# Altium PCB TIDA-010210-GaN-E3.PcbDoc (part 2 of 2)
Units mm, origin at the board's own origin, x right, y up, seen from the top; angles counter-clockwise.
Board outline 75 x 60 mm, 4 copper layers (Top Layer, MidLayer1, MidLayer2, Bottom Layer), stack 1.554 mm thick; 107 components, 49 nets, 409 pads, 513 vias.
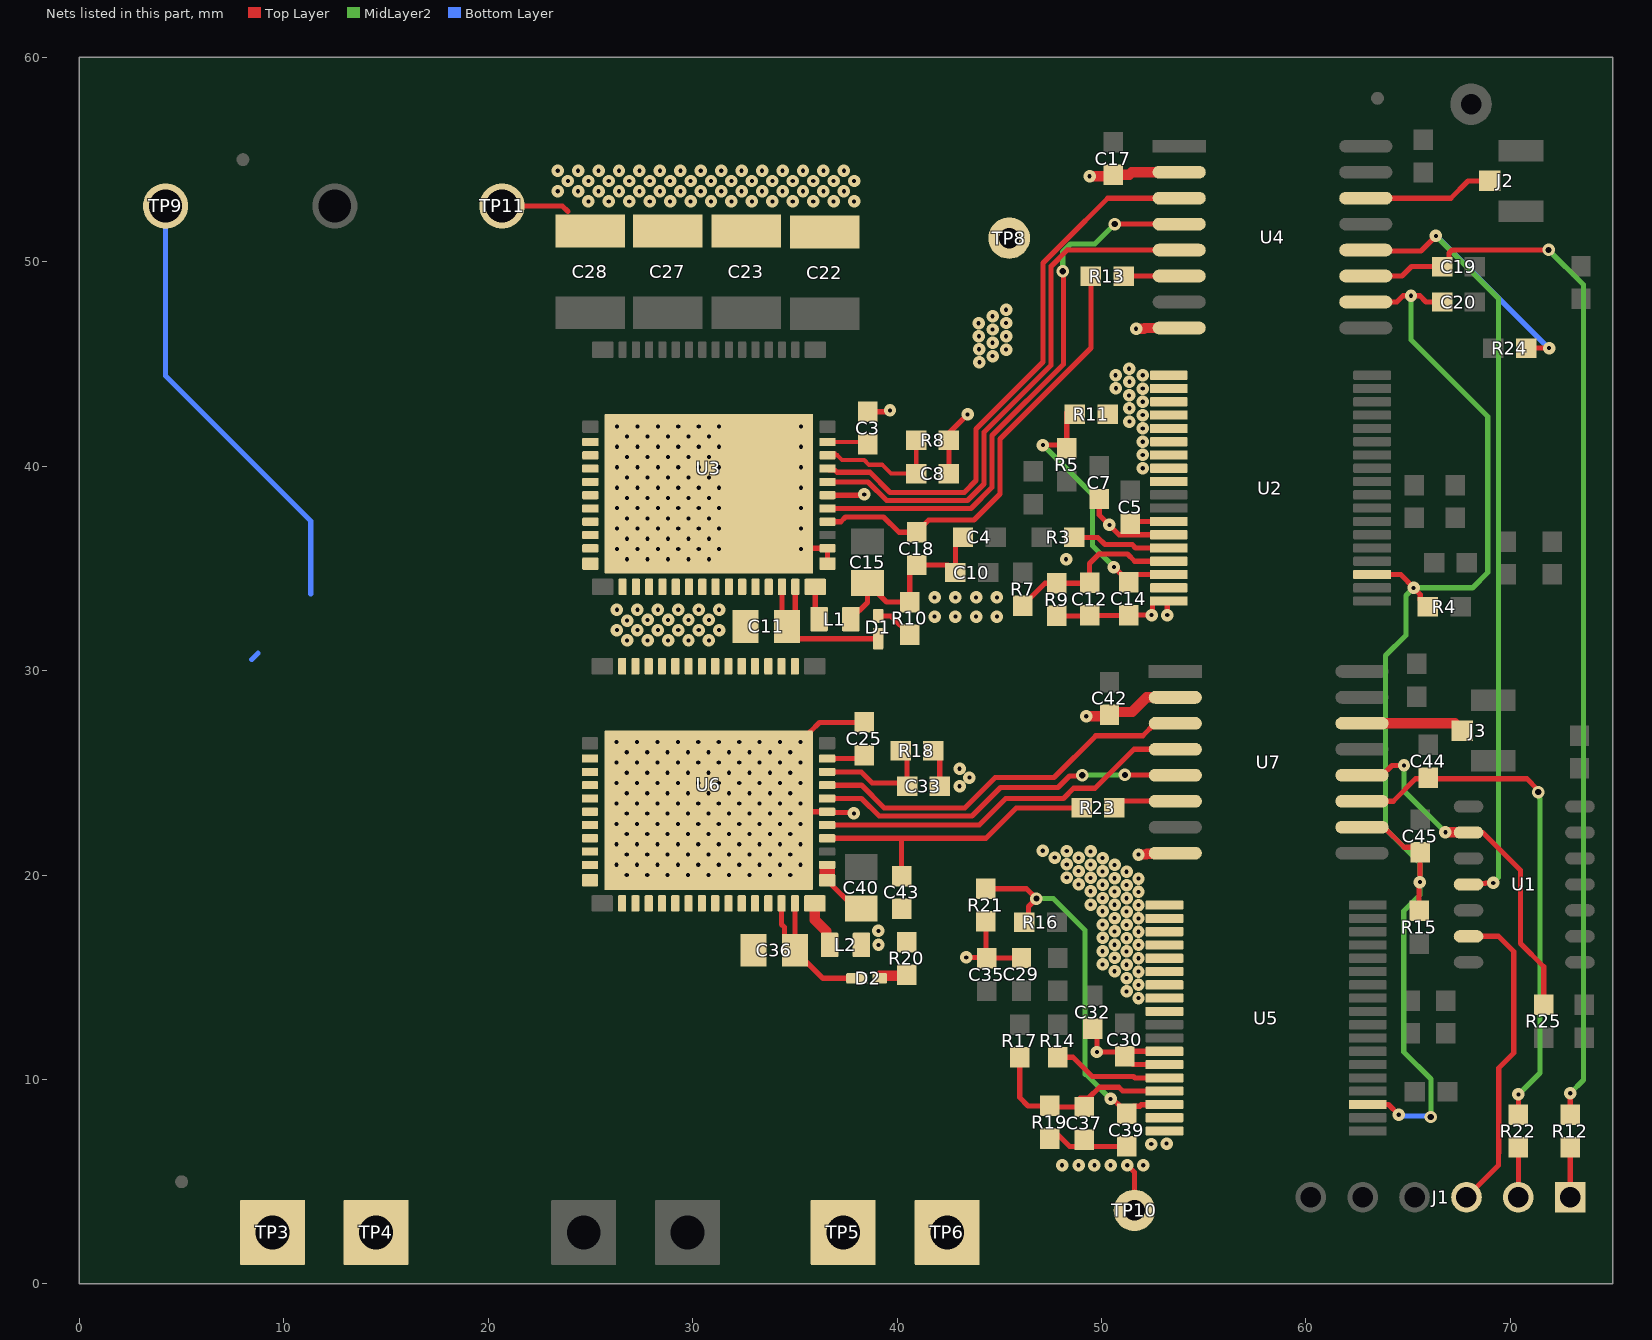
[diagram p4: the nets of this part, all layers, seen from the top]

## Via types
v1: diameter 0.61, hole 0.203, Top Layer to Bottom Layer, tented both sides, 497 vias
v2: diameter 0.61, hole 0.305, Top Layer to Bottom Layer, tented both sides, 16 vias

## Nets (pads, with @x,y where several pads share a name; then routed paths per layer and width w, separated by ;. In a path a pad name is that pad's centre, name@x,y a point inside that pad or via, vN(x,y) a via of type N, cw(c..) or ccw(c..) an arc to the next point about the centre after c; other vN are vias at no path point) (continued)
Low_Rail: C22.2 C23.2 C25.1 C27.2 C28.2 C29.2 C30.2 C32.2 C33.1 C35.2 C36.1 C37.2 C39.2 C40.2 C42.2 C43.2 L2.1 R18.2 R19.1 R20.1 R21.1 TP5.1 TP6.1 TP10.1 TP11.1 U5.19 U5.20 U5.21 U5.22 U5.23 U5.24 U5.25 U5.26 U5.27 U5.30 U5.31 U5.35 U5.36 U6.18 U6.19 U6.20 U6.21 U6.22 U6.23 U6.24 U6.25 U6.26 U6.27 U6.29 U6.30 U6.31 U6.32 U6.33 U6.34 U6.35 U6.36 U6.37 U6.38 U6.39 U6.40 U6.44 U6.45 U6.49 U6.55 U7.2 U7.8 | length 38.3
  Top Layer w0.254: TP11.1@20.676,52.73 23.624,52.73 23.897,52.458 ; v1(35.275,23.507) 35.682,23.1 U6.49@36.575,23.1 36.614,23.061 37.85,23.061 v1(37.89,23.021) ; U6.44@36.575,19.75 37.96,18.365 C40.2@38.251,18.365 ; C25.1@38.401,27.469 36.202,27.469 35.748,27.015 35.748,26.938 U6.55@35.317,26.507 ; C33.1@42.086,24.349 R18.2@42.086,26.074 ; v1(43.382,15.974) 44.312,15.974 C35.2@44.341,15.946 ; R21.1@44.341,17.732 C35.2@44.341,15.946 ; C29.2@45.981,15.946 C35.2@44.341,15.946 ; R19.1@47.681,7.493 48.445,6.729 49.293,6.729 C39.2@51.259,6.729 ; C32.2@49.477,12.578 49.773,12.281 v1(49.773,11.347) 50.926,11.347 C30.2@51.138,11.135 ; v1(51.259,5.809) 51.606,5.463 TP10.1@51.606,3.601 ; U5.31@53.076,10.732 51.541,10.732 51.511,10.762 51.486,10.762 51.138,11.11 C30.2@51.138,11.135 ; U5.30@53.076,11.382 51.385,11.382 C30.2@51.138,11.135 ; U6.55@35.317,26.507 v1(35.275,26.507) U6.55@35.317,26.507
  Top Layer w0.508: v1(49.25,27.768) 50.314,27.768 C42.2@50.39,27.844 50.525,27.979 51.499,27.979 52.213,28.693 U7.2@53.609,28.693 ; v1(51.808,21.007) 52.189,21.007 52.233,21.051 53.587,21.051 U7.8@53.609,21.073
  Top Layer w0.75: U6.44@36.575,19.9 U6.45@36.575,20.3
  other v1: 48.074,5.809 48.875,5.809 49.653,5.809 50.444,5.809 52.038,5.809 52.434,6.843 53.183,6.866 51.808,13.982 51.222,14.314 51.808,14.632 51.222,14.964 50.637,15.296 51.808,15.282 51.222,15.614 50.052,15.628 50.637,15.946 51.808,15.932 50.052,16.278 51.222,16.264 39.09,16.582 51.808,16.582 50.637,16.596 51.222,16.914 50.052,16.928 50.637,17.246 51.808,17.232 39.084,17.27 50.052,17.578 51.222,17.564 51.808,17.882 50.637,17.896 51.222,18.214 50.052,18.228 50.637,18.546 51.808,18.532 49.467,18.561 51.222,18.864 50.052,18.878 51.808,19.182 50.637,19.196 49.467,19.211 50.052,19.528 51.222,19.514 48.881,19.543 51.808,19.832 49.467,19.861 50.637,19.846 48.296,19.875 26.775,20.007 27.775,20.007 28.775,20.007 29.775,20.007 30.775,20.007 31.775,20.007 32.775,20.007 33.775,20.007 34.775,20.007 51.222,20.164 48.881,20.193 50.052,20.178 50.637,20.496 26.275,20.507 27.275,20.507 28.275,20.507 29.275,20.507 30.275,20.507 31.275,20.507 32.275,20.507 33.275,20.507 34.275,20.507 35.275,20.507 48.296,20.525 49.467,20.511 50.052,20.828 47.711,20.857 48.881,20.843 26.775,21.007 27.775,21.007 28.775,21.007 29.775,21.007 30.775,21.007 31.775,21.007 32.775,21.007 33.775,21.007 34.775,21.007 49.467,21.161 47.125,21.189 48.296,21.175 26.275,21.507 27.275,21.507 28.275,21.507 29.275,21.507 30.275,21.507 31.275,21.507 32.275,21.507 33.275,21.507 34.275,21.507 35.275,21.507 26.775,22.007 27.775,22.007 28.775,22.007 29.775,22.007 30.775,22.007 31.775,22.007 32.775,22.007 33.775,22.007 34.775,22.007 26.275,22.507 27.275,22.507 28.275,22.507 29.275,22.507 30.275,22.507 31.275,22.507 32.275,22.507 33.275,22.507 34.275,22.507 35.275,22.507 26.775,23.007 27.775,23.007 28.775,23.007 29.775,23.007 30.775,23.007 31.775,23.007 32.775,23.007 33.775,23.007 34.775,23.007 26.275,23.507 27.275,23.507 28.275,23.507 29.275,23.507 30.275,23.507 31.275,23.507 32.275,23.507 33.275,23.507 34.275,23.507 26.775,24.007 27.775,24.007 28.775,24.007 29.775,24.007 30.775,24.007 31.775,24.007 32.775,24.007 33.775,24.007 34.775,24.007 43.055,24.349 26.275,24.507 27.275,24.507 28.275,24.507 29.275,24.507 30.275,24.507 31.275,24.507 32.275,24.507 33.275,24.507 34.275,24.507 35.275,24.507 43.54,24.768 26.775,25.007 27.775,25.007 28.775,25.007 29.775,25.007 30.775,25.007 31.775,25.007 32.775,25.007 33.775,25.007 34.775,25.007 43.055,25.2 26.275,25.507 27.275,25.507 28.275,25.507 29.275,25.507 30.275,25.507 31.275,25.507 32.275,25.507 33.275,25.507 34.275,25.507 35.275,25.507 26.775,26.007 27.775,26.007 28.775,26.007 29.775,26.007 30.775,26.007 31.775,26.007 32.775,26.007 33.775,26.007 34.775,26.007 26.275,26.507 27.275,26.507 28.275,26.507 29.275,26.507 30.275,26.507 31.275,26.507 32.275,26.507 33.275,26.507 34.275,26.507 24.897,52.953 25.897,52.953 26.897,52.953 27.897,52.953 28.897,52.953 29.897,52.953 30.897,52.953 31.897,52.953 32.897,52.953 33.897,52.953 34.897,52.953 35.897,52.953 36.897,52.953 37.897,52.953 23.397,53.453 24.397,53.453 25.397,53.453 26.397,53.453 27.397,53.453 28.397,53.453 29.397,53.453 30.397,53.453 31.397,53.453 32.397,53.453 33.397,53.453 34.397,53.453 35.397,53.453 36.397,53.453 37.397,53.453 23.897,53.953 24.897,53.953 25.897,53.953 26.897,53.953 27.897,53.953 28.897,53.953 29.897,53.953 30.897,53.953 31.897,53.953 32.897,53.953 33.897,53.953 34.897,53.953 35.897,53.953 36.897,53.953 37.897,53.953 23.397,54.453 24.397,54.453 25.397,54.453 26.397,54.453 27.397,54.453 28.397,54.453 29.397,54.453 30.397,54.453 31.397,54.453 32.397,54.453 33.397,54.453 34.397,54.453 35.397,54.453 36.397,54.453 37.397,54.453
NetC3_2: C3.2 U3.53 | length 2
  Top Layer w0.203: U3.53@36.596,41.185 38.437,41.185 C3.2@38.555,41.067
NetC8_2: C8.2 R8.1 U3.52 | length 6.7
  Top Layer w0.203: U3.52@36.953,40.634 36.694,40.634 U3.52@36.596,40.535 37.076,40.535 37.309,40.303 38.392,40.303 38.625,40.07 39.277,40.07 39.708,39.639 C8.2@40.936,39.639 R8.1@40.936,41.271
NetC11_2: C11.2 D1.1 U3.41 U3.42 | length 9.1
  Top Layer w0.254: U3.41@34.371,34.1 34.371,32.837 C11.2@35.021,32.187 ; C11.2@34.612,32.166 C11.2@35.042,32.166 ; U3.42@35.021,34.1 C11.2@35.021,32.187 ; D1.1@39.075,31.563 35.12,31.563 35.042,31.641 C11.2@35.042,32.166 ; C11.2@35.021,32.187 C11.2@35.042,32.166
NetC12_1: C12.1 R7.1 R9.2 U2.33 | length 8.9
  Top Layer w0.254: R7.1@46.147,33.183 47.242,34.278 R9.2@47.817,34.278 49.389,34.278 C12.1@49.414,34.303 49.414,35.244 49.875,35.705 51.273,35.705 51.627,35.352 U2.33@53.286,35.352
NetC14_1: C14.1 R5.2 R11.2 U2.34 | length 13.6
  Top Layer w0.254: v1(47.135,41.038) 48.131,41.038 R5.2@48.296,40.873 48.296,42.624 R11.2@48.297,42.625 ; v1(50.604,35.068) 51.329,34.343 C14.1@51.329,34.318 51.713,34.702 U2.34@53.286,34.702
  MidLayer2 w0.254: v1(47.135,41.038) 49.563,38.61 49.563,36.109 v1(50.604,35.068)
NetC18_1: C18.1 R13.2 U3.47 | length 22.1
  Top Layer w0.254: U3.47@36.596,37.285 37.243,37.285 37.477,37.519 39.34,37.519 40.09,36.769 C18.1@40.955,36.769 41.551,37.366 43.758,37.366 45.037,38.645 45.037,41.339 49.478,45.78 R13.2@49.478,49.303
NetC19_1: C19.1 R12.2 U4.11 | length 52.9
  Top Layer w0.254: U4.11@62.929,49.303 64.704,49.303 65.164,49.763 C19.1@66.662,49.763 67,50.102 67,50.43 67.149,50.579 v2(71.868,50.579) ; R12.2@72.931,8.282 v1(72.931,9.331)
  MidLayer2 w0.254: v2(71.868,50.579) 73.57,48.877 73.57,9.97 v1(72.931,9.331)
NetC20_1: C20.1 C45.1 R4.2 R15.1 U2.3 U4.10 U5.3 U7.10 | length 64.3
  Top Layer w0.254: U7.10@62.74,22.343 63.824,22.343 64.804,21.364 65.342,21.364 C45.1@65.598,21.109 65.573,21.084 v1(65.573,19.655) 65.534,19.617 R15.1@65.534,18.246 ; U4.10@62.929,48.033 64.442,48.033 64.747,48.338 65.573,48.338 65.878,48.033 C20.1@66.662,48.033 ; U5.3@63.026,8.782 64.037,8.782 v1(64.542,8.278) ; U2.3@63.236,34.702 64.64,34.702 65.29,34.052 v1(65.261,34.052) 65.588,33.725 65.588,33.473 65.965,33.096 R4.2@65.989,33.096
  MidLayer2 w0.254: v1(65.138,48.338) 65.138,46.192 68.896,42.434 68.896,34.805 68.143,34.052 v1(65.261,34.052) 64.886,33.677 64.886,31.736 63.897,30.747 63.897,22.271 65.573,20.595 v1(65.573,19.655) 65.573,19.034 64.783,18.245 64.783,11.347 66.109,10.021 v2(66.109,8.168)
  Bottom Layer w0.254: v1(64.542,8.278) 64.596,8.223 66.054,8.223 v2(66.109,8.168)
NetC25_2: C25.2 U6.53 | length 1.9
  Top Layer w0.254: U6.53@36.575,25.7 38.233,25.7 C25.2@38.401,25.869
NetC33_2: C33.2 R18.1 U6.52 | length 5.9
  Top Layer w0.254: U6.52@36.575,25.05 38.242,25.05 38.785,24.507 40.329,24.507 C33.2@40.486,24.349 R18.1@40.486,26.074
NetC36_2: C36.2 D2.1 U6.41 U6.42 | length 8.1
  Top Layer w0.254: U6.41@34.35,18.615 34.35,17.588 34.493,17.445 34.493,16.995 34.55,16.939 C36.2@35,16.939 ; C36.2@35,16.322 35,16.487 C36.2@35,16.939 ; U6.42@35,18.615 C36.2@35,16.939 ; C36.2@35.001,16.281 C36.2@35.448,15.835 ; C36.2@35.468,15.854 36.372,14.95 D2.1@38.035,14.95
NetC37_1: C37.1 R17.1 R19.2 U5.33 | length 9.8
  Top Layer w0.254: R17.1@45.996,11.091 45.996,9.116 46.4,8.712 R19.2@47.462,8.712 47.518,8.656 C37.1@49.163,8.656 ; C37.1@48.945,9.095 49.366,9.095 49.896,9.625 50.842,9.625 51.035,9.432 U5.33@53.076,9.432
NetC39_1: C39.1 R16.2 R21.2 U5.34 | length 19.1
  Top Layer w0.254: R21.2@44.341,19.332 46.334,19.332 v2(46.812,18.853) 46.429,18.47 46.429,17.899 R16.2@46.222,17.692 ; v1(50.444,9.054) 50.512,8.986 50.623,8.986 50.907,8.702 50.911,8.702 51.259,8.354 C39.1@51.259,8.329 ; C39.1@51.234,8.329 51.234,8.354 51.574,8.694 51.874,8.694 51.947,8.767 53.061,8.767 U5.34@53.076,8.782
  MidLayer2 w0.254: v2(46.812,18.853) 47.636,18.853 49.186,17.304 49.186,10.258 49.239,10.258 v1(50.444,9.054)
NetC43_1: C43.1 R23.2 U6.47 | length 14.9
  Top Layer w0.254: U6.47@36.575,21.8 40.218,21.8 ; C43.1@40.218,19.951 40.218,21.8 ; R23.2@49.026,23.289 45.83,23.289 44.341,21.8 40.218,21.8
NetC44_1: C44.1 R22.2 U7.11 | length 25.7
  Top Layer w0.254: U7.11@62.74,23.613 64.266,23.613 65.371,24.718 65.977,24.718 70.797,24.718 71.36,24.155 v2(71.36,24.059) ; R22.2@70.391,8.282 v1(70.391,9.27)
  MidLayer2 w0.254: v1(70.391,9.27) 71.447,10.326 71.447,23.732 71.428,23.752 71.428,23.991 v2(71.36,24.059)
NetD1_2: D1.2 R10.2 | length 1.9
  Top Layer w0.254: D1.2@39.075,32.678 39.698,32.678 R10.2@40.623,31.753
NetD2_2: D2.2 R20.2 | length 1.3
  Top Layer w0.508: D2.2@39.155,15.084 40.443,15.084 R20.2@40.48,15.121
NetJ1_3: J1.3 U1.6 | length 15.5
  Top Layer w0.254: J1.3@67.851,4.242 69.419,5.809 69.419,6.394 69.429,6.404 69.429,10.561 70.168,11.3 70.168,16.257 69.419,17.006 U1.6@67.952,17.006
NetL1_2: L1.2 U3.43 | length 1.7
  Top Layer w0.254: U3.43@35.996,34.1 35.996,32.712 L1.2@36.186,32.522
NetL2_2: L2.2 U6.43 | length 2.3
  Top Layer w0.508: U6.43@35.975,18.615 35.975,17.807 36.53,17.252 36.53,16.753 L2.2@36.701,16.582
NetR3_1: R3.1 U2.32 | length 4.8
  Top Layer w0.254: R3.1@48.672,36.519 49.815,36.519 50.165,36.17 51.499,36.17 51.667,36.002 U2.32@53.286,36.002
NetR13_1: R13.1 U4.6 | length 2.7
  Top Layer w0.254: R13.1@51.078,49.303 U4.6@53.798,49.303
NetR14_1: R14.1 U5.32 | length 5.6
  Top Layer w0.254: R14.1@47.853,11.091 48.611,11.091 49.547,10.154 51.562,10.154 51.634,10.082 U5.32@53.076,10.082
NetR23_1: R23.1 U7.6 | length 2.8
  Top Layer w0.254: R23.1@50.842,23.629 53.593,23.629 U7.6@53.609,23.613
NetU3_48: U3.48 U4.4 | length 27.7
  Top Layer w0.254: U3.48@36.596,37.935 43.609,37.935 44.643,38.97 44.643,41.502 48.133,44.992 48.133,49.507 v2(48.098,49.542) ; v2(50.643,51.843) U4.4@53.798,51.843
  MidLayer2 w0.254: v2(48.098,49.542) 48.098,50.487 48.477,50.865 49.665,50.865 v2(50.643,51.843)
NetU3_50: U3.50 U4.5 | length 27
  Top Layer w0.254: U3.50@36.596,39.235 38.583,39.235 39.489,38.329 43.446,38.329 44.25,39.133 44.25,41.665 47.527,44.942 47.527,49.778 48.322,50.573 U4.5@53.798,50.573
NetU3_51: U3.51 U4.3 | length 28
  Top Layer w0.254: U3.51@36.596,39.885 36.669,39.812 36.945,39.812 37.055,39.702 38.673,39.702 39.652,38.723 43.283,38.723 43.856,39.296 43.856,41.828 47.133,45.105 47.133,49.941 48.159,50.967 50.305,53.113 U4.3@53.798,53.113
NetU6_48: U6.48 U7.4 | length 18.6
  Top Layer w0.254: U6.48@36.575,22.45 44.017,22.45 45.317,23.75 48.134,23.75 48.634,24.25 49.683,24.25 51.586,26.153 U7.4@53.609,26.153
NetU6_50: U6.50 U7.5 | length 18.2
  Top Layer w0.254: U6.50@36.575,23.75 38.265,23.75 39.124,22.891 43.66,22.891 45.051,24.283 47.866,24.283 48.432,24.848 49.022,24.848 v2(49.057,24.883) ; v2(51.141,24.9) 53.592,24.9 U7.5@53.609,24.883
  MidLayer2 w0.254: v2(49.057,24.883) 49.065,24.892 51.133,24.892 v2(51.141,24.9)
NetU6_51: U6.51 U7.3 | length 19.2
  Top Layer w0.254: U6.51@36.575,24.4 38.252,24.4 39.367,23.285 43.313,23.285 44.804,24.776 47.679,24.776 49.721,26.818 52.014,26.818 52.619,27.423 U7.3@53.609,27.423
O\C\_\H\S\_\I\S\O\: R24.2 U1.4 U4.12 | length 46.9
  Top Layer w0.254: U4.12@62.929,50.573 62.972,50.53 65.622,50.53 v1(66.355,51.264) ; U1.4@67.952,19.546 67.996,19.589 68.753,19.589 68.781,19.617 v1(69.162,19.617) ; R24.2@70.769,45.78 v1(71.889,45.78)
  MidLayer2 w0.254: v1(66.355,51.264) 69.419,48.2 69.419,19.898 69.162,19.641 v1(69.162,19.617)
  Bottom Layer w0.254: v1(66.355,51.264) 66.38,51.264 71.864,45.78 v1(71.889,45.78)
O\C\_\L\S\_\I\S\O\: R25.2 U1.2 U7.12 | length 17.9
  Top Layer w0.254: U7.12@62.74,24.883 63.73,24.883 64.215,25.368 v1(64.796,25.368) ; U1.2@67.952,22.086 68.644,22.086 70.49,20.24 70.49,16.657 71.63,15.518 R25.2@71.63,13.653
  Top Layer w0.508: v1(66.821,22.093) 67.945,22.093 U1.2@67.952,22.086
  MidLayer2 w0.254: v1(64.796,25.368) 64.796,24.118 v1(66.821,22.093)
PWM_HS_ISO: J1.1 R12.1 | length 2.4
  Top Layer w0.254: J1.1@72.931,4.242 R12.1@72.931,6.682
PWM_LS_ISO: J1.2 R22.1 | length 2.4
  Top Layer w0.254: J1.2@70.391,4.242 R22.1@70.391,6.682
SW_Rail: C3.1 C4.2 C5.2 C7.2 C8.1 C10.2 C11.1 C12.2 C14.2 C15.2 C17.2 C18.2 L1.1 R8.2 R9.1 R10.1 R11.1 TP3.1 TP4.1 TP8.1 TP9.1 U2.19 U2.20 U2.21 U2.22 U2.23 U2.24 U2.25 U2.26 U2.27 U2.30 U2.31 U2.35 U2.36 U3.18 U3.19 U3.20 U3.21 U3.22 U3.23 U3.24 U3.25 U3.26 U3.27 U3.29 U3.30 U3.31 U3.32 U3.33 U3.34 U3.35 U3.36 U3.37 U3.38 U3.39 U3.40 U3.44 U3.45 U3.49 U3.55 U4.2 U4.8 U6.2 U6.3 U6.4 U6.5 U6.6 U6.7 U6.8 U6.9 U6.10 U6.11 U6.12 U6.13 U6.14 U6.15 | length 60.9
  Top Layer w0.254: v1(35.296,35.952) 35.329,35.985 U3.45@36.596,35.985 U3.44@36.596,35.235 ; U3.49@36.596,38.585 38.357,38.585 v1(38.391,38.619) ; L1.1@37.736,32.522 38.555,33.342 C15.2@38.555,34.285 39.487,33.353 R10.1@40.623,33.353 40.623,34.838 C18.2@40.955,35.169 42.481,35.169 42.831,34.82 C10.2@42.849,34.802 42.85,34.803 42.85,36.17 43.199,36.519 C4.2@43.224,36.519 ; C3.1@38.555,42.667 39.589,42.667 v1(39.652,42.73) ; C8.1@42.536,39.639 R8.2@42.536,41.271 42.536,41.624 v1(43.446,42.534) ; R9.1@47.817,32.678 49.389,32.678 C12.2@49.414,32.703 51.315,32.703 C14.2@51.329,32.718 v1(52.447,32.718) 52.492,32.763 52.492,33.304 52.59,33.402 U2.36@53.286,33.402 53.217,33.333 v1(53.217,32.719) ; C7.2@49.889,38.398 49.889,37.623 50.86,36.652 U2.31@53.286,36.652 ; C5.2@51.462,37.194 51.569,37.302 U2.30@53.286,37.302
  Top Layer w0.508: v1(49.414,54.186) 50.501,54.186 C17.2@50.564,54.25 51.353,54.25 51.487,54.383 U4.2@53.798,54.383 ; v1(51.689,46.725) 52.07,46.725 52.108,46.763 U4.8@53.798,46.763
  Bottom Layer w0.254: TP9.1@4.216,52.73 4.216,44.427 11.317,37.327 11.317,33.75 ; 8.432,30.546 8.735,30.849
  other v1: 26.796,31.482 27.796,31.482 28.796,31.482 29.796,31.482 30.796,31.482 26.296,31.982 27.296,31.982 28.296,31.982 29.296,31.982 30.296,31.982 31.296,31.982 26.796,32.452 27.796,32.482 28.796,32.482 29.796,32.482 30.796,32.482 41.836,32.643 42.851,32.643 43.866,32.643 44.881,32.643 26.296,32.982 27.296,32.982 28.296,32.982 29.296,32.982 30.296,32.982 31.296,32.982 41.836,33.583 42.851,33.583 43.866,33.583 44.881,33.583 26.796,35.452 27.796,35.452 28.796,35.452 29.796,35.452 30.796,35.452 48.268,35.452 26.296,35.952 27.296,35.952 28.296,35.952 29.296,35.952 30.296,35.952 31.296,35.952 26.796,36.452 27.796,36.452 28.796,36.452 29.796,36.452 30.796,36.452 26.296,36.952 27.296,36.952 28.296,36.952 29.296,36.952 30.296,36.952 31.296,36.952 35.296,36.952 50.381,37.131 26.796,37.452 27.796,37.452 28.796,37.452 29.796,37.452 30.796,37.452 26.296,37.952 27.296,37.952 28.296,37.952 29.296,37.952 30.296,37.952 31.296,37.952 35.296,37.952 26.796,38.452 27.796,38.452 28.796,38.452 29.796,38.452 30.796,38.452 26.296,38.952 27.296,38.952 28.296,38.952 29.296,38.952 30.296,38.952 31.296,38.952 35.296,38.952 26.796,39.452 27.796,39.452 28.796,39.452 29.796,39.452 30.796,39.452 52.018,39.902 26.296,39.952 27.296,39.952 28.296,39.952 29.296,39.952 30.296,39.952 31.296,39.952 35.296,39.952 26.796,40.452 27.796,40.452 28.796,40.452 29.796,40.452 30.796,40.452 52.018,40.552 26.296,40.952 27.296,40.952 28.296,40.952 29.296,40.952 30.296,40.952 31.296,40.952 35.296,40.952 52.018,41.202 26.796,41.452 27.796,41.452 28.796,41.452 29.796,41.452 30.796,41.452 52.018,41.852 26.296,41.952 27.296,41.952 28.296,41.952 29.296,41.952 30.296,41.952 31.296,41.952 35.296,41.952 51.36,42.184 52.018,42.502 51.36,42.834 52.018,43.152 51.347,43.469 50.702,43.816 52.018,43.802 51.36,44.134 50.689,44.451 52.018,44.452 51.347,44.769 44.026,45.087 44.671,45.39 44.013,45.722 45.329,45.707 44.671,46.04 44,46.357 45.329,46.357 44.671,46.69 43.987,46.992 45.329,47.007 44.671,47.34 45.329,47.657
TEMP_HS_ISO: J2.1 U4.14 | length 6.4
  Top Layer w0.254: U4.14@62.929,53.113 67.079,53.113 67.921,53.956 J2.1@68.985,53.956
TEMP_LS_ISO: J3.1 U7.14 | length 5
  Top Layer w0.508: U7.14@62.74,27.423 67.282,27.423 J3.1@67.637,27.068
pads on no net: FID1.1 FID2.1 FID3.1 J2.2@70.51,55.456 J2.3@70.51,52.456 J3.2@69.162,28.568 J3.3@69.162,25.568 U1.3 U1.8 U1.11 U3.1 U3.16 U3.17 U3.28 U3.54 U6.1 U6.16 U6.17 U6.28 U6.54

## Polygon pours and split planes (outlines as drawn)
Low_Rail on MidLayer1 "MidLayer1-Low_Rail" (solid, remove dead copper, pour order 140): 12.294,39.167 18.247,45.12 18.318,51.626 23.092,56.4 36.134,56.4 38.036,54.497 38.036,30.825 43.493,25.368 46.351,25.368 48.781,27.798 48.781,29.881 49.546,30.646 51.63,30.646 53.275,30.646 54.162,29.76 54.162,7.419 52.204,5.461 46.601,5.461 44.977,7.085 44.977,9.499 36.269,18.208 35.89,17.829 44.429,9.089 44.341,1 37.646,1 32.104,6.542 25.429,6.542 12.294,19.678 12.294,27.613
SW_Rail on MidLayer1 "SW_RAIL_L02_P133" (solid, remove dead copper, pour order 133): 35.021,33.182 35.108,33.182 37.122,31.168 37.173,31.22 42.596,31.22 43.488,32.111 53.106,32.111 54.613,33.618 54.613,56.126 54.441,56.126 53.643,56.924 50.008,56.924 48.902,55.818 43.54,50.455 43.54,43.812 43.045,43.317 37.904,43.317 35.876,43.317 35.876,43.245 35,42.368 35.021,42.348
GND_ISO on MidLayer1 "GND_ISO_L02_P096" (solid, remove dead copper, pour order 96): 58.842,4.236 60.691,6.085 61.395,6.085 62.113,6.804 62.113,56.924 63.686,58.496 72.72,58.496 74.581,56.635 74.581,3.165 72.501,1.085 58.842,1.085
Low_Rail on Top Layer "LOW_RAIL_L01_P104" (solid, remove dead copper, pour order 104): 35.773,1 35.773,6.202 23.388,18.587 23.388,27.122 24.465,28.195 34.594,28.195 36.121,26.669 36.121,17.374 44.485,9.01 44.485,1.144 44.341,1
SW_Rail on Top Layer "SW_RAIL_L01_P151" (solid, pour order 151): 52.375,34.239 52.375,32.512 54.204,32.512 54.204,34.239
SW_Rail on Top Layer "SW_RAIL_L01_P148" (solid, remove dead copper, pour order 148): 40.227,33.182 43.177,33.182 43.177,35.258 42.733,35.702 39.734,35.702 37.535,33.503 37.535,32.097 38.143,32.097 38.144,32.618 38.708,33.182
SW_Rail on Top Layer "SW_RAIL_L01_P147" (solid, remove dead copper, pour order 147): 45.19,32.083 45.198,33.773 44.988,33.983 41.552,33.983 41.316,33.747 41.316,31.66 41.756,31.22 42.596,31.22 43.488,32.111 43.516,32.083
Low_Rail on Top Layer "Top Layer-Low_Rail" (solid, remove dead copper, pour order 144): 50.229,21.65 52.06,19.82 54.207,19.82 54.207,18.846 54.207,13.388 53.952,13.133 52.088,13.133 51.43,13.792 48.752,16.47 48.752,18.772 46.309,21.215 46.309,21.513 46.446,21.65 49.187,21.65
Low_Rail on Top Layer "LOW_RAIL_L01_P146" (solid, remove dead copper, pour order 146): 38.051,16.117 38.051,17.41 37.888,17.573 37.235,17.573 36.979,17.829 36.979,18.599 37.302,18.922 40.336,18.922 40.623,18.635 40.623,16.592 40.148,16.117
Low_Rail on Top Layer "LOW_RAIL_L01_P145" (solid, remove dead copper, pour order 145): 43.287,23.658 43.905,24.276 43.905,24.704 42.241,26.368 41.963,26.368 41.963,23.969 42.273,23.658
Low_Rail on Top Layer "LOW_RAIL_L01_P139" (solid, remove dead copper, pour order 139): 46.358,7.315 46.569,7.529 48.735,7.529 49.057,7.206 51.662,7.206 51.984,7.529 51.984,8.393 52.093,8.502 54.141,8.502 54.251,8.392 54.162,8.303 54.162,7.419 52.204,5.461 46.591,5.461 46.323,5.729
SW_Rail on Top Layer "SW_RAIL_L01_P134" (solid, remove dead copper, pour order 134): 54.162,39.053 52.298,39.053 51.64,39.712 51.64,41.397 50.047,42.989 50.047,45.222 54.173,45.222 54.417,44.978 54.417,39.308
GND_ISO on Top Layer "GND_ISO_L01_P130" (solid, remove dead copper, pour order 130): 64.963,28.269 70.168,28.269 70.168,29.972 69.81,30.329 67.093,30.329 65.978,29.214 62.759,29.214 62.421,28.876 62.421,28.391 62.553,28.264
GND_ISO on Top Layer "GND_ISO_L01_P129" (solid, remove dead copper, pour order 129): 62.771,10.258 67.511,10.258 67.837,10.584 67.837,13.629 67.887,13.629 68.471,14.214 69.033,14.214 69.245,14.002 69.217,13.974 69.217,12.306 68.952,12.042 68.952,7.213 68.371,6.632 67.012,6.632 66.513,7.132 66.513,7.795 66.795,8.078 66.795,9.508 66.458,9.845 62.771,9.845
12V_ISO on Top Layer "12V_ISO_L01_P128" (solid, remove dead copper, pour order 128): 62.335,11.403 62.335,10.732 67.244,10.732 67.319,10.807 67.319,11.786 66.841,12.264 65.133,12.258 64.278,11.403
no net on Top Layer "NONET_L01_P127" (solid, remove dead copper, pour order 127): 62.335,11.514 62.335,10.574 62.321,10.561
GND_ISO on Top Layer "GND_ISO_L01_P126" (solid, remove dead copper, pour order 126): 66.794,13.127 69.03,13.127 69.245,13.342 69.245,14.002 68.934,14.312 66.786,14.312 65.361,15.737 64.449,15.737 64.449,18.887 64.244,19.093 64.225,19.074 62.077,19.074 62.077,13.629 62.335,13.371 66.55,13.371
SW_Rail on Top Layer "SW_RAIL_L01_P120" (solid, remove dead copper, pour order 120): 35.276,29.666 35.276,30.498 34.842,30.932 34.785,30.875 33.87,30.875 33.476,31.27 33.476,34.279 34.086,34.89 35.786,34.89 35.786,42.588 35.113,43.261 25.249,43.261 24.315,42.326 24.315,30.714 25.362,29.666
High_Rail on Top Layer "HIGH_RAIL_L01_P117" (solid, remove dead copper, pour order 117): 31.341,1 31.391,1.049 31.391,5.078 21.699,14.77 19.962,16.507 19.962,42.356 23.161,45.555 37.451,45.555 38.401,46.506 38.401,48.148 38.154,48.395 21.561,48.395 12.497,39.331 12.497,19.435 22.905,9.026 22.905,1
Low_Rail on Top Layer "LOW_RAIL_L01_P111" (solid, remove dead copper, pour order 111): 23.282,51.41 22.941,51.751 22.941,55.016 23.324,55.399 37.667,55.399 38.53,54.536 38.53,51.67 38.273,51.414
GND_ISO on Top Layer "GND_ISO_L01_P100" (solid, remove dead copper, pour order 100): 63.951,6.085 64.661,6.796 64.661,7.541 64.346,7.856 63.993,7.856 63.993,8.005 63.653,8.346 63.585,8.278 62.113,8.278 62.113,6.394 62.421,6.085
GND_ISO on Top Layer "GND_ISO_L01_P099" (solid, remove dead copper, pour order 99): 61.717,21.109 61.742,21.084 63.993,21.084 63.993,21.061 64.542,20.512 64.542,19.391 63.946,18.795 63.946,12.248 63.569,11.871 62.274,11.871 62.077,12.068 62.077,19.545 61.717,19.905
GND_ISO on Top Layer "GND_ISO_L01_P098" (solid, remove dead copper, pour order 98): 62.771,31.993 63.07,31.694 63.405,31.688 63.631,31.914 64.136,32.418 64.136,34.142 62.335,34.142 62.335,32.4
GND_ISO on Top Layer "GND_ISO_L01_P097" (solid, remove dead copper, pour order 97): 68.079,38.602 68.531,39.053 68.531,44.979 68.118,45.392 62.802,45.392 62.462,45.052 62.462,38.189 62.929,37.723 63.814,37.723 64.693,38.602
SW_Rail on Bottom Layer "Bottom Layer-SW_Rail" (solid, remove dead copper, pour order 152): 49.836,35.275 50.733,34.378 51.127,34.378 51.36,34.611 51.36,34.93 50.008,36.282 50.008,38.604 47.893,40.719 47.893,40.977 47.418,41.452 46.812,41.452 46.658,41.297 46.658,40.982 49.281,38.359 49.283,36.251 48.077,36.251 47.817,35.99 47.817,35.442 48.231,35.028 49.589,35.028
SW_Rail on Bottom Layer "SW_RAIL_L04_P118" (solid, remove dead copper, pour order 118): 7.226,1 7.226,30.992 10.245,34.01 38.91,34.01 38.91,30.636 38.226,29.951 11.78,29.951 10.414,28.585 10.414,9.437 16.101,3.75 16.101,1
Low_Rail on Bottom Layer "LOW_RAIL_L04_P131" (solid, remove dead copper, pour order 131): 48.077,19.133 48.417,19.472 50.284,19.472 50.466,19.289 50.466,18.554 49.563,17.651 49.563,8.932 50.926,7.569 50.926,6.37 50.459,5.903 47.462,5.903 47.233,6.132 47.233,6.819 48.752,8.337 48.752,17.37 48.062,18.059 48.062,19.118
GND_ISO on Bottom Layer "GND_ISO_L04_P125" (solid, remove dead copper, pour order 125): 58.842,4.236 60.691,6.085 61.395,6.085 62.113,6.804 62.113,56.924 63.686,58.496 72.72,58.496 74.581,56.635 74.581,3.165 72.501,1.085 58.842,1.085
SW_Rail on Bottom Layer "SW_RAIL_L04_P107" (solid, remove dead copper, pour order 107): 22.352,44.384 24.425,46.456 36.449,46.456 38.89,44.015 38.89,31.389 38.169,30.668 22.941,30.668 22.316,31.293 22.352,31.329
Low_Rail on Bottom Layer "LOW_RAIL_L04_P110" (solid, remove dead copper, pour order 110): 22.247,27.016 23.495,28.264 37.361,28.264 38.785,26.84 38.785,17.894 35.814,14.922 25.016,14.923 22.247,17.692
SW_Rail on MidLayer2 "SW_RAIL_L03_P132" (solid, remove dead copper, pour order 132): 23.594,29.793 37.712,29.793 39.138,31.22 42.596,31.22 43.459,32.083 53.078,32.083 54.523,33.528 54.523,56.216 54.351,56.216 53.643,56.924 49.281,56.924 43.54,51.182 43.54,43.812 42.988,43.261 37.961,43.261 23.563,43.261 22.403,42.1 22.403,30.985
Low_Rail on MidLayer2 "LOW_RAIL_L03_P141" (solid, remove dead copper, pour order 141): 48.779,27.734 48.779,29.879 49.546,30.646 51.692,30.646 53.275,30.646 54.162,29.76 54.162,7.419 52.204,5.461 46.601,5.461 44.977,7.085 44.977,9.499 37.477,16.999 23.092,16.999 23.06,16.967 22.454,17.573 22.352,17.573 22.352,27.145 23.402,28.195 40.666,28.195 43.493,25.368 46.413,25.368

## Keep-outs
Keep-Out Layer:
  text ".Layer_Name" at 11.481,-35.478 h1.52

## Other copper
Top Layer:
  text ".Layer_Name" at 11.557,-35.63 h1.52
MidLayer1:
  pour cut-out: 25.241,42.869 25.841,43.469 31.872,43.469 32.335,43.006 32.335,31.034 31.104,29.804 26.487,29.804 25.26,31.031
  text ".Layer_Name" at 11.532,-35.58 h1.52
MidLayer2:
  text ".Layer_Name" at 11.43,-35.529 h1.52
Bottom Layer:
  text ".Layer_Name" at 11.532,-35.58 h1.52

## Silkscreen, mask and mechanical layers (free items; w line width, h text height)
Top Overlay:
  circle w0.254: c14.828,11.3 r2.25
  circle w0.254: c14.8,46.36 r2.25
  circle w0.254: c45.072,28.8 r2.25
  lines w0.254: 41.103,28.683 41.596,28.19 ; 41.242,44.459 41.735,43.966 ; 41.597,28.18 41.597,30.174 ; 41.607,28.18 42.1,28.674 ; 41.736,44.013 41.736,43.956 ; 41.736,45.95 41.736,43.956 ; 42.239,44.45 41.746,43.957 41.746,43.956 41.736,43.956
  text ".PRJ_Number" at 1.517,57.15 h3.05
  text "VER: .PCB_Rev" at 25.841,57.15 h3.05
  text "V+" at 11.325,49.175 h2.54
  text "SW" at 2.075,48.775 h2.54
  text "V-" at 20.111,48.663 h2.54
  text "12V" at 68.175,39.066 h0.64
  text "12V" at 37.395,37.438 h0.64
  text "12V" at 38.922,21.665 h0.64 r90
  text "5V" at 64.719,5.359 h1.27
  text "AGND" at 58.039,5.258 h1.27
  text "12V" at 61.824,5.232 h1.27
  text "PWM1A" at 74.625,5.182 h1.27 r90
  text "FAULT" at 68.986,5.156 h1.27 r90
  text "PWM1B" at 72.085,5.156 h1.27 r90
  text "V+" at 26.34,4.877 h1.52
  text "V-" at 39.268,4.862 h1.52
  text "VSW" at 10.414,4.801 h1.52
  text ".Layer_Name" at 11.659,-35.681 h1.52
Bottom Overlay:
  lines w0.152: 11.074,44.907 11.709,44.247 ; 11.709,44.247 11.684,44.272 11.43,44.272 11.709,44.552 11.709,44.247
  lines w0.381: 52.294,8.89 12.294,8.89 12.294,48.89 52.294,48.89
  text "HeatSink" at 9.931,44.221 h0.64 r270
  text "PWM1B" at 70.027,5.524 h1.27 r270
  text "12V" at 62.452,5.512 h1.27 r270
  text "5V" at 64.922,5.486 h1.27 r270
  text "PWM1A" at 72.695,5.486 h1.27 r270
  text "FAULT" at 67.437,5.461 h1.27 r270
  text "AGND" at 59.868,5.385 h1.27 r270
  text "V+" at 28.118,4.902 h1.52
  text "V-" at 40.97,4.862 h1.52
  text "VSW" at 13.614,4.821 h1.52
  text ".Layer_Name" at 11.582,-35.402 h1.52
Top Paste:
  text ".Layer_Name" at 11.481,-35.478 h1.52
Bottom Paste:
  text ".Layer_Name" at 11.481,-35.478 h1.52
Top Solder:
  text ".Layer_Name" at 11.481,-35.478 h1.52
Bottom Solder:
  rectangle: 12.497,9.093 52.095,48.692
  text ".Layer_Name" at 11.481,-35.478 h1.52
Drill Guide:
  text ".Layer_Name" at 11.481,-35.58 h1.52
M1 Board Outline:
  lines w0.127: 13.3,11.3 cw(c14.8,11.3) 14.8,12.8 cw(c14.8,11.3) 16.3,11.3 cw(c14.8,11.3) 14.8,9.8 cw(c14.8,11.3) 13.3,11.3 ; 13.3,46.3 cw(c14.8,46.3) 14.8,47.8 cw(c14.8,46.3) 16.3,46.3 cw(c14.8,46.3) 14.8,44.8 cw(c14.8,46.3) 13.3,46.3 ; 43.6,28.8 cw(c45.1,28.8) 45.1,30.3 cw(c45.1,28.8) 46.6,28.8 cw(c45.1,28.8) 45.1,27.3 cw(c45.1,28.8) 43.6,28.8
  lines w0.15: 0,0 75,0 75,60 0,60 0,0
M2 Board Dimensions:
  rectangle: -3.048,-20.911 0.127,-17.736
  rectangle: 0,-24.099 9.525,-20.924
  lines w0.178: -3.175,-17.749 -3.175,-24.099 22.225,-24.099 22.225,-17.749 ; -3.048,-20.911 22.352,-20.911 ; -3.048,-17.736 22.352,-17.736 ; 0,-24.099 0,-17.749 ; 3.175,-24.099 3.175,-17.749 ; 9.525,-24.099 9.525,-17.749 ; 15.875,-24.099 15.875,-17.749
M3 3D STEP Top:
  text ".Layer_Name" at 11.481,-35.478 h1.52
M5 Assembly Top:
  circle w0.254: c50.084,27.875 r0.193
  lines w0.254: -10.592,-37.298 157.048,-37.298 ; -10.592,-32.134 157.099,-32.134 ; -10.592,-26.969 -10.592,-42.463 91.135,-42.463 157.099,-42.463 157.099,-26.969 -10.579,-26.969 -10.579,-42.463 29.439,-42.463 ; 52.019,-42.463 52.019,-26.969 ; 84.201,-32.134 84.201,-26.969 ; 105.537,-32.134 105.537,-26.969 ; 121.336,-42.628 121.336,-37.476
  text "COMPONENTS MARKED 'DNP' SHOULD NOT BE POPULATED." at 26.124,-21.762 h0.46
  text "ASSEMBLY VARIANT:" at 26.111,-24.696 h0.46
  text ".VariantName" at 52.426,-24.696 h0.46
  text "PCB VIEWED FROM TOP SIDE" at -8.979,-30.326 h0.46
  text "BOARD #:" at 53.924,-30.326 h0.46
  text ".PRJ_Number" at 67.78,-30.326 h0.46
  text "REV:" at 89.23,-30.326 h0.46
  text ".PCB_Rev" at 96.634,-30.326 h0.46
  text "SVN REV:" at 110.515,-30.326 h0.46
  text ".VersionControl_RevNumber" at 123.368,-30.326 h0.46
  text ".Layer_Name" at 11.285,-35.463 h0.46
  text "TID #:" at 53.924,-35.491 h0.46
  text ".TID" at 67.78,-35.491 h0.46
  text "LAYER NAME =" at -8.979,-35.529 h0.46
  text "PLOT NAME =" at -8.979,-40.706 h0.46
  text ".plot_File_Name" at 11.481,-40.706 h0.46
  text "GENERATED    :" at 53.975,-40.706 h0.46
  text ".Print_Date" at 76.06,-40.706 h0.46
  text ".Print_Time" at 94.577,-40.706 h0.46
  text "TEXAS INSTRUMENTS" at 126.695,-40.706 h0.46
M6 Assembly Bottom:
  circle w0.254: c72.923,5.029 r0.234
  lines w0.254: -10.604,-32.146 157.086,-32.146 ; -10.554,-37.311 157.086,-37.311 ; 25.159,-42.641 25.159,-37.489 ; 40.957,-32.146 40.957,-26.982 ; 62.293,-32.146 62.293,-26.982 ; 94.475,-42.476 94.475,-26.982 ; 117.056,-42.476 157.074,-42.476 157.074,-26.982 -10.604,-26.982 -10.604,-42.476 55.359,-42.476 157.086,-42.476 157.086,-26.982
  text "COMPONENTS MARKED 'DNP' SHOULD NOT BE POPULATED." at 156.769,-21.851 h0.46
  text ".VariantName" at 130.251,-24.797 h0.46
  text "ASSEMBLY VARIANT:" at 156.642,-24.797 h0.46
  text ".VersionControl_RevNumber" at 23.127,-30.339 h0.46
  text "SVN REV:" at 35.979,-30.339 h0.46
  text ".PCB_Rev" at 49.86,-30.339 h0.46
  text "REV:" at 57.264,-30.339 h0.46
  text ".PRJ_Number" at 78.715,-30.339 h0.46
  text "BOARD #:" at 92.57,-30.339 h0.46
  text "PCB VIEWED FROM BOTTOM SIDE" at 155.473,-30.339 h0.46
  text ".Layer_Name" at 146.667,-34.879 h0.46
  text "LAYER NAME =" at 155.207,-35.148 h0.46
  text ".TID" at 78.715,-35.503 h0.46
  text "TID #:" at 92.57,-35.503 h0.46
  text "TEXAS INSTRUMENTS" at 19.799,-40.719 h0.46
  text ".Print_Time" at 51.918,-40.719 h0.46
  text ".Print_Date" at 70.434,-40.719 h0.46
  text "GENERATED    :" at 92.519,-40.719 h0.46
  text ".plot_File_Name" at 135.014,-40.719 h0.46
  text "PLOT NAME =" at 155.473,-40.719 h0.46
M9 Title Sheet:
  drawing of 57 lines, arcs and shapes, not listed
  text "1" at 15.617,190.455 h1.78
  text "2" at 79.007,190.455 h1.78
  text "3" at 142.236,190.455 h1.78
  text "4" at 205.905,190.455 h1.78
  text "5" at 269.38,190.455 h1.78
  text "6" at 333.007,190.455 h1.78
  text "A" at -13.754,161.423 h1.78
  text "A" at 362.166,161.423 h1.78
  text "B" at -13.754,100.971 h1.78
  text "B" at 362.166,100.971 h1.78
  text "C" at 362.166,40.646 h1.78
  text "PROJECT TITLE:" at 284.95,-6.624 h1.14
  text ".PRJ_Title" at 286.22,-10.01 h1.78
  text "DESIGNED FOR:" at 284.95,-14.269 h1.14
  text ".PRJ_Customer" at 286.22,-17.825 h1.78
  text "D" at -13.754,-19.552 h1.78
  text "D" at 362.166,-19.552 h1.78
  text "FILE NAME:" at 284.95,-21.889 h1.14
  text ".PCB_File_Name_No_Path" at 286.22,-24.937 h1.78
  text "Texas Instruments (TI) and/or its licensors do not warrant the accuracy or completeness of this specification" at 158.725,-29.048 h1.14
  text "ENGINEER:" at 284.95,-29.255 h1.14
  text "LAYOUT BY:" at 323.177,-29.255 h1.14
  text "or any information contained therein. TI and/or its licensors do not warrant that this design will meet" at 157.582,-31.909 h1.14
  text ".PRJ_Engineer" at 286.22,-33.192 h1.78
  text ".PCB_Layout" at 324.46,-33.192 h1.78
  text "the specifications, will be suitable for your application or fit for any particular purpose, or will operate in" at 157.582,-34.771 h1.14
  text "ALTIUM DESIGNER VERSION:" at 323.177,-37.129 h1.14
  text "an implementation. TI and/or its licensors do not warrant that the design is production worthy. You should" at 157.582,-37.633 h1.14
  text "completely validate and test your design implementation to confirm the system functionality for your application." at 158.725,-40.495 h1.14
  text ".print_Scale" at 286.22,-40.516 h1.78
  text ".Application_BuildNumber" at 324.46,-40.516 h1.78
  text "1" at 15.617,-45.765 h1.78
  text "2" at 79.007,-45.765 h1.78
  text "3" at 142.236,-45.765 h1.78
  text "4" at 205.905,-45.765 h1.78
  text "5" at 269.38,-45.765 h1.78
  text "6" at 333.007,-45.765 h1.78
M10 Fab Notes:
  drawing of 227 lines, arcs and shapes, not listed
  text "DESIGN INFORMATION" at 311.086,159.286 h1.52
  text "(REFER ALSO ARRAY/PANEL PROFILING INFORMATION)" at 302.157,155.067 h1.52
  text "BOARD SIZE" at 284.733,154.958 h1.52
  text "75MM" at 297.408,152.13 h1.52
  text "60MM" at 313.258,151.952 h1.52
  text "X" at 309.32,151.712 h1.52
  text "Number of Layers :" at 294.969,146.703 h1.52
  text "4" at 322.212,146.576 h1.52
  text "6" at 322.235,143.229 h1.52
  text "MIN. TRACK WIDTH:" at 294.969,143.173 h1.52
  text "MIL" at 326.745,143.173 h1.52
  text "MIN. CLEARANCE:" at 294.969,139.82 h1.52
  text "MIL" at 326.745,139.82 h1.52
  text "5.5" at 320.98,139.776 h1.52
  text "8" at 322.377,136.652 h1.52
  text "MIN. VIA DRILL SIZE:" at 294.969,136.467 h1.52
  text "MIL" at 326.745,136.467 h1.52
  text "4 MIL" at 312.622,132.868 h1.52
  text "MINIMUM ANNULAR RING" at 286.607,132.759 h1.52
  text "EXTERNAL" at 335.267,132.479 h1.52
  text "PER" at 291.687,129.762 h1.52
  text "IPC-D-275 CLASS 2 LEVEL C" at 297.275,129.762 h1.52
  text "MIL, HOLES" at 335.076,126.91 h1.52
  text "+/-" at 325.107,126.891 h1.52
  text "+/-" at 346.799,126.891 h1.52
  text "REGISTRATION TOLERANCES:" at 286.607,126.764 h1.52
  text "METAL" at 317.081,126.764 h1.52
  text "5" at 331.716,126.764 h1.52
  text "3" at 352.875,126.764 h1.52
  text "MIL" at 355.828,126.764 h1.52
  text "MATERIAL:" at 284.708,121.444 h1.52
  text "FR-4 High Tg" at 309.763,117.88 h1.52
  text "FR-408" at 295.401,117.662 h1.52
  text "X" at 305.727,117.671 h1.52
  text "OTHER" at 333.196,117.662 h1.52
  text "63 MIL (1.6mm) +/-10%" at 303.532,113.529 h1.52
  text "THICKNESS:" at 286.607,113.42 h1.52
  text "X" at 300.276,113.42 h1.52
  text "OTHER" at 336.168,113.42 h1.52
  text "TOLERANCE:" at 286.607,109.407 h1.52
  text "X" at 307.925,109.407 h1.52
  text "ANSI IPC-6012 TYPE 3 CLASS 2" at 312.673,109.407 h1.52
  text "OTHER +/-" at 312.673,105.445 h1.52
  text "BOW & TWIST:" at 286.607,101.457 h1.52
  text "X" at 307.925,101.457 h1.52
  text "ANSI IPC-6012 TYPE 3 CLASS 2" at 312.673,101.457 h1.52
  text "OTHER +/-" at 312.673,97.431 h1.52
  text "COPPER THICKNESS (FINISHED):" at 284.708,93.989 h1.52
  text "1.4MIL (1oz)" at 307.06,90.11 h1.52
  text "2MIL (1.4oz)" at 326.541,90.11 h1.52
  text "2.8MIL (2oz)" at 345.007,90.11 h1.52
  text "OUTER:" at 293.775,90.001 h1.52
  text "X" at 341.612,89.951 h1.52
  text "1.4MIL (1oz)" at 307.06,86.122 h1.52
  text "2.8MIL (2oz)" at 326.541,86.122 h1.52
  text "N/A" at 344.995,86.132 h1.52
  text "INNER SIGNAL:" at 286.433,86.014 h1.52
  text "X" at 323.095,85.989 h1.52
  text "DRILLING:" at 284.708,82.483 h1.52
  text "REFERENCE:" at 286.607,79.511 h1.52
  text "X" at 303.072,79.511 h1.52
  text "AS SHOWN" at 307.822,79.511 h1.52
  text "X" at 325.957,79.511 h1.52
  text "NC_DRILL FILES" at 329.437,79.511 h1.52
  text "PTH MIN COPPER THICKNESS:" at 286.607,75.498 h1.52
  text "X" at 320.903,75.498 h1.52
  text "1MIL" at 324.382,75.498 h1.52
  text "OTHER" at 337.006,75.498 h1.52
  text "BOARD FINISH:" at 284.708,71.459 h1.52
  text "X" at 325.648,68.564 h1.52
  text "SILKSCREEN:" at 288.65,68.462 h1.52
  text "X" at 312.749,68.462 h1.52
  text "TOP" at 315.95,68.462 h1.52
  text "BOTTOM" at 328.929,68.462 h1.52
  text "SILKSCREEN COLOR:" at 288.65,64.22 h1.52
  text "X" at 312.723,64.22 h1.52
  text "WHITE" at 315.95,64.22 h1.52
  text "OTHER" at 328.929,64.22 h1.52
  text "SOLDER RESIST COLOR:" at 288.65,59.902 h1.52
  text "X" at 303.071,55.859 h1.52
  text "GREEN" at 306.298,55.859 h1.52
  text "BLUE" at 321.309,55.859 h1.52
  text "OTHER" at 334.974,55.859 h1.52
  text "IMMERSION GOLD (ENIG)" at 311.657,51.07 h1.52
  text "ENEPIG" at 345.63,50.987 h1.52
  text "SURFACE FINISH:" at 284.708,50.962 h1.52
  text "X" at 306.909,50.962 h1.52
  text "IMM. TIN/SILVER OR EQUIV" at 293.078,46.974 h1.52
  text "OTHER" at 329.437,46.974 h1.52
  text "X" at 306.806,42.554 h1.52
  text "ARRAY/PANEL:" at 284.708,42.427 h1.52
  text "CUT AND TRIM PER MECH LAYER 1" at 311.657,42.318 h1.52
  text "N.C. ROUTE" at 311.657,38.465 h1.52
  text "V. SCORE" at 333.653,38.465 h1.52
  text "CERTIFICATION:" at 284.708,34.985 h1.52
  text "MATERIALS AND WORKMANSHIP FOR ALL PCBS" at 303.123,34.985 h1.52
  text "TO MEET OR EXCEED THE REQUIREMENTS OF:" at 303.123,32.496 h1.52
  text "X" at 293.636,29.029 h1.52
  text "ANSI IPC-A-600F CLASS ->" at 297.166,29.029 h1.52
  text "X" at 338.798,29.029 h1.52
  text "2" at 341.82,29.029 h1.52
  text "1" at 333.819,28.991 h1.52
  text "3" at 350.811,28.991 h1.52
  text "X" at 293.688,24.977 h1.52
  text "UL 94V-0" at 297.166,24.977 h1.52
  text "X" at 314.313,24.977 h1.52
  text "RoHS" at 317.791,24.977 h1.52
  text "OTHER" at 334.159,24.977 h1.52
  text "PER ORDER" at 344.244,24.977 h1.52
  text "VIA TENTING:" at 315.633,21.583 h1.52
  text "X" at 335.255,21.473 h1.52
  text "ADDITIONAL REQUIREMENTS:" at 284.708,21.396 h1.52
  text "YES" at 329.595,21.352 h1.52
  text "NO" at 338.861,21.22 h1.52
  text "MICROSECTION:" at 286.607,18.475 h1.52
  text "YES" at 309.612,18.475 h1.52
  text "IMPEDANCE CONTROL:" at 316.192,18.306 h1.52
  text "YES" at 341.185,18.281 h1.52
  text "X" at 354.952,18.103 h1.52
  text "NO" at 350.723,17.841 h1.52
  text "REQUIRED" at 331.494,14.509 h1.52
  text "BARE BOARD ELEC. TEST:" at 286.607,14.436 h1.52
  text "NONE" at 319.772,14.436 h1.52
  text "X" at 328.269,14.436 h1.52
  text "PER ORDER" at 346.531,14.436 h1.52
  text "MANUFACTURER'S UL:" at 286.607,10.449 h1.52
  text "RAIL" at 316.216,10.34 h1.52
  text "METAL" at 328.708,10.34 h1.52
  text "X" at 338.239,10.331 h1.52
  text "SILK" at 341.705,10.34 h1.52
M11 Gerber Information:
  lines w0.254: -10.592,-37.298 157.048,-37.298 ; -10.592,-32.134 157.099,-32.134 ; -10.592,-26.969 -10.592,-42.463 91.135,-42.463 157.099,-42.463 157.099,-26.969 -10.579,-26.969 -10.579,-42.463 29.439,-42.463 ; 52.019,-42.463 52.019,-26.969 ; 84.201,-32.134 84.201,-26.969 ; 105.537,-32.134 105.537,-26.969 ; 121.336,-42.628 121.336,-37.476
  text ".PRJ_Number" at 66.58,-30.227 h1.02
  text "ALL ARTWORK VIEWED FROM TOP SIDE" at -8.979,-30.326 h1.52
  text "BOARD #:" at 53.924,-30.326 h1.52
  text "SVN REV:" at 110.515,-30.326 h1.52
  text ".VersionControl_RevNumber" at 123.368,-30.326 h1.52
  text "REV:" at 96.044,-30.688 h1.52
  text "LAYER NAME =" at -8.979,-35.478 h1.52
  text "TID #:" at 53.924,-35.491 h1.52
  text ".TID" at 67.78,-35.491 h1.52
  text "PLOT NAME =" at -8.979,-40.706 h1.52
  text ".plot_File_Name" at 9.23,-40.706 h1.52
  text "GENERATED    :" at 53.975,-40.706 h1.52
  text ".Print_Date" at 76.06,-40.706 h1.52
  text ".Print_Time" at 94.577,-40.706 h1.52
  text "TEXAS INSTRUMENTS" at 126.695,-40.706 h1.52
M12 Stackup:
  drawing of 295 lines, arcs and shapes, not listed
  text "Layer" at 80.419,97.333 h1.52
  text "Name" at 90.83,97.333 h1.52
  text "Material" at 114.446,97.333 h1.52
  text "Thickness" at 136.284,97.333 h1.52
  text "Constant" at 152.79,97.333 h1.52
  text "Board Layer Stack" at 167.264,97.333 h1.52
  text "Top Overlay" at 90.83,94.285 h1.52
  text "Top Solder" at 90.83,91.237 h1.52
  text "Solder Resist" at 114.446,91.237 h1.52
  text "0.40mil" at 136.284,91.237 h1.52
  text "3.5" at 152.79,91.237 h1.52
  text "1" at 80.419,88.189 h1.52
  text "Top Layer" at 90.83,88.189 h1.52
  text "2.80mil" at 136.284,88.189 h1.52
  text "Dielectric1" at 90.83,85.141 h1.52
  text "FR-4 High Tg" at 114.446,85.141 h1.52
  text "10.00mil" at 136.284,85.141 h1.52
  text "4.8" at 152.79,85.141 h1.52
  text "2" at 80.419,82.093 h1.52
  text "MidLayer1" at 90.83,82.093 h1.52
  text "2.80mil" at 136.284,82.093 h1.52
  text "Dielectric2" at 90.83,79.045 h1.52
  text "FR-4 High Tg" at 114.446,79.045 h1.52
  text "30.00mil" at 136.284,79.045 h1.52
  text "4.8" at 152.79,79.045 h1.52
  text "3" at 80.419,75.997 h1.52
  text "MidLayer2" at 90.83,75.997 h1.52
  text "2.80mil" at 136.284,75.997 h1.52
  text "Dielectric3" at 90.83,72.949 h1.52
  text "FR-4 High Tg" at 114.446,72.949 h1.52
  text "10.00mil" at 136.284,72.949 h1.52
  text "4.8" at 152.79,72.949 h1.52
  text "4" at 80.419,69.901 h1.52
  text "Bottom Layer" at 90.83,69.901 h1.52
  text "2.80mil" at 136.284,69.901 h1.52
  text "Bottom Solder" at 90.83,66.853 h1.52
  text "Solder Resist" at 114.446,66.853 h1.52
  text "0.40mil" at 136.284,66.853 h1.52
  text "3.5" at 152.79,66.853 h1.52
  text "Bottom Overlay" at 90.83,63.805 h1.52
M13 Component Bodies Top:
  text ".Layer_Name" at 11.481,-35.478 h1.52
M14 Component Bodies Bottom:
  text ".Layer_Name" at 11.481,-35.478 h1.52
M16 Courtyards Bottom:
  text ".Layer_Name" at 11.481,-35.478 h1.52
Drill Drawing:
  circle w0.254: c80.532,41.851 r0.7
  lines w0.254: 79.832,29.95 81.232,29.95 80.532,28.55 79.832,29.95 ; 79.832,32.05 80.182,32.05 80.532,31.7 80.882,32.05 81.232,32.05 80.882,32.4 81.232,32.75 80.882,32.75 80.532,33.101 80.182,32.75 79.832,32.75 80.182,32.4 79.832,32.05 ; 79.832,35.201 80.182,35.201 80.182,34.851 80.882,34.851 80.882,35.201 81.232,35.201 81.232,35.901 80.882,35.901 80.882,36.251 80.182,36.251 80.182,35.901 79.832,35.901 79.832,35.201 ; 79.832,38.001 81.232,38.001 81.232,39.401 79.832,39.401 79.832,38.001 ; 79.832,44.302 80.532,44.652 81.232,44.302 80.882,45.002 81.232,45.702 80.532,45.352 79.832,45.702 80.182,45.002 79.832,44.302
  lines w0.305: 78.562,27.605 160.523,27.605 ; 78.562,46.507 160.523,46.507 ; 87.131,24.455 87.131,49.657 ; 95.556,24.455 95.556,49.657 ; 111.707,24.455 111.707,49.657 ; 118.28,24.455 118.28,49.657 ; 127.799,24.455 127.799,49.657 ; 146.152,24.455 146.152,49.657 ; 78.562,24.455 160.523,24.455 160.523,49.657 78.562,49.657 78.562,24.455
  text "Drill Table" at 111.658,51.384 h1.52
  text "Symbol" at 80.452,47.452 h1.83
  text "Quantity" at 88.076,47.452 h1.83
  text "Finished Hole Size" at 96.501,47.452 h1.83
  text "Plated" at 112.652,47.452 h1.83
  text "Hole Type" at 119.225,47.452 h1.83
  text "Drill Layer Pair" at 128.744,47.452 h1.83
  text "Hole Tolerance" at 147.097,47.452 h1.83
  text "497" at 88.076,44.302 h1.52
  text "8.00mil (0.203mm)" at 96.501,44.302 h1.52
  text "PTH" at 112.652,44.302 h1.52
  text "Round" at 119.225,44.302 h1.52
  text "Top Layer - Bottom Layer" at 128.744,44.302 h1.52
  text "16" at 88.076,41.151 h1.52
  text "12.00mil (0.305mm)" at 96.501,41.151 h1.52
  text "PTH" at 112.652,41.151 h1.52
  text "Round" at 119.225,41.151 h1.52
  text "Top Layer - Bottom Layer" at 128.744,41.151 h1.52
  text "6" at 88.076,38.001 h1.52
  text "39.37mil (1.000mm)" at 96.501,38.001 h1.52
  text "PTH" at 112.652,38.001 h1.52
  text "Round" at 119.225,38.001 h1.52
  text "Top Layer - Bottom Layer" at 128.744,38.001 h1.52
  text "3" at 88.076,34.851 h1.52
  text "40.00mil (1.016mm)" at 96.501,34.851 h1.52
  text "PTH" at 112.652,34.851 h1.52
  text "Round" at 119.225,34.851 h1.52
  text "Top Layer - Bottom Layer" at 128.744,34.851 h1.52
  text "3" at 88.076,31.7 h1.52
  text "63.00mil (1.600mm)" at 96.501,31.7 h1.52
  text "PTH" at 112.652,31.7 h1.52
  text "Round" at 119.225,31.7 h1.52
  text "Top Layer - Bottom Layer" at 128.744,31.7 h1.52
  text "6" at 88.076,28.55 h1.52
  text "64.96mil (1.650mm)" at 96.501,28.55 h1.52
  text "PTH" at 112.652,28.55 h1.52
  text "Round" at 119.225,28.55 h1.52
  text "Top Layer - Bottom Layer" at 128.744,28.55 h1.52
  text "531 Total" at 88.076,25.4 h1.52
  text ".Layer_Name" at 11.481,-35.478 h1.52

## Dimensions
0,0 to 75,0 on M2 Board Dimensions
0,0 to 0,60 on M2 Board Dimensions
-3.175,-24.099 to 22.225,-24.099 on M2 Board Dimensions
